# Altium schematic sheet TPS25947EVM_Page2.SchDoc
size 431 x 279 mm; Date: Not shown in title block; ApprovedBy: Not shown in title block; CheckedBy: Not shown in title block; Author: Not shown in title block; CompanyName: Not shown in title block; Engineer: Not shown in title block; Organization: Not shown in title block; Address1: Not shown in title block; Address2: Not shown in title block; Address3: Not shown in title block; Address4: Not shown in title block; DocumentNumber: 2; Revision: Use project parameter SCH_Rev; SheetNumber: 2; SheetTotal: 3; PageSetup: Record=PageOptions¦CenterHorizontal=True¦CenterVertical=True¦PrintScale=1.00¦XCorrection=1.00¦YCorrection=1.00¦PrintKind=0¦BorderSize=5000000¦LeftOffset=0¦BottomOffset=0¦Orientation=2¦PaperLength=1000¦PaperWidth=1000¦Scale=100¦PaperSource=15¦PrintQuality=600¦MediaType=1¦DitherType=10¦PaperKind=Letter¦PrintScaleMode=1
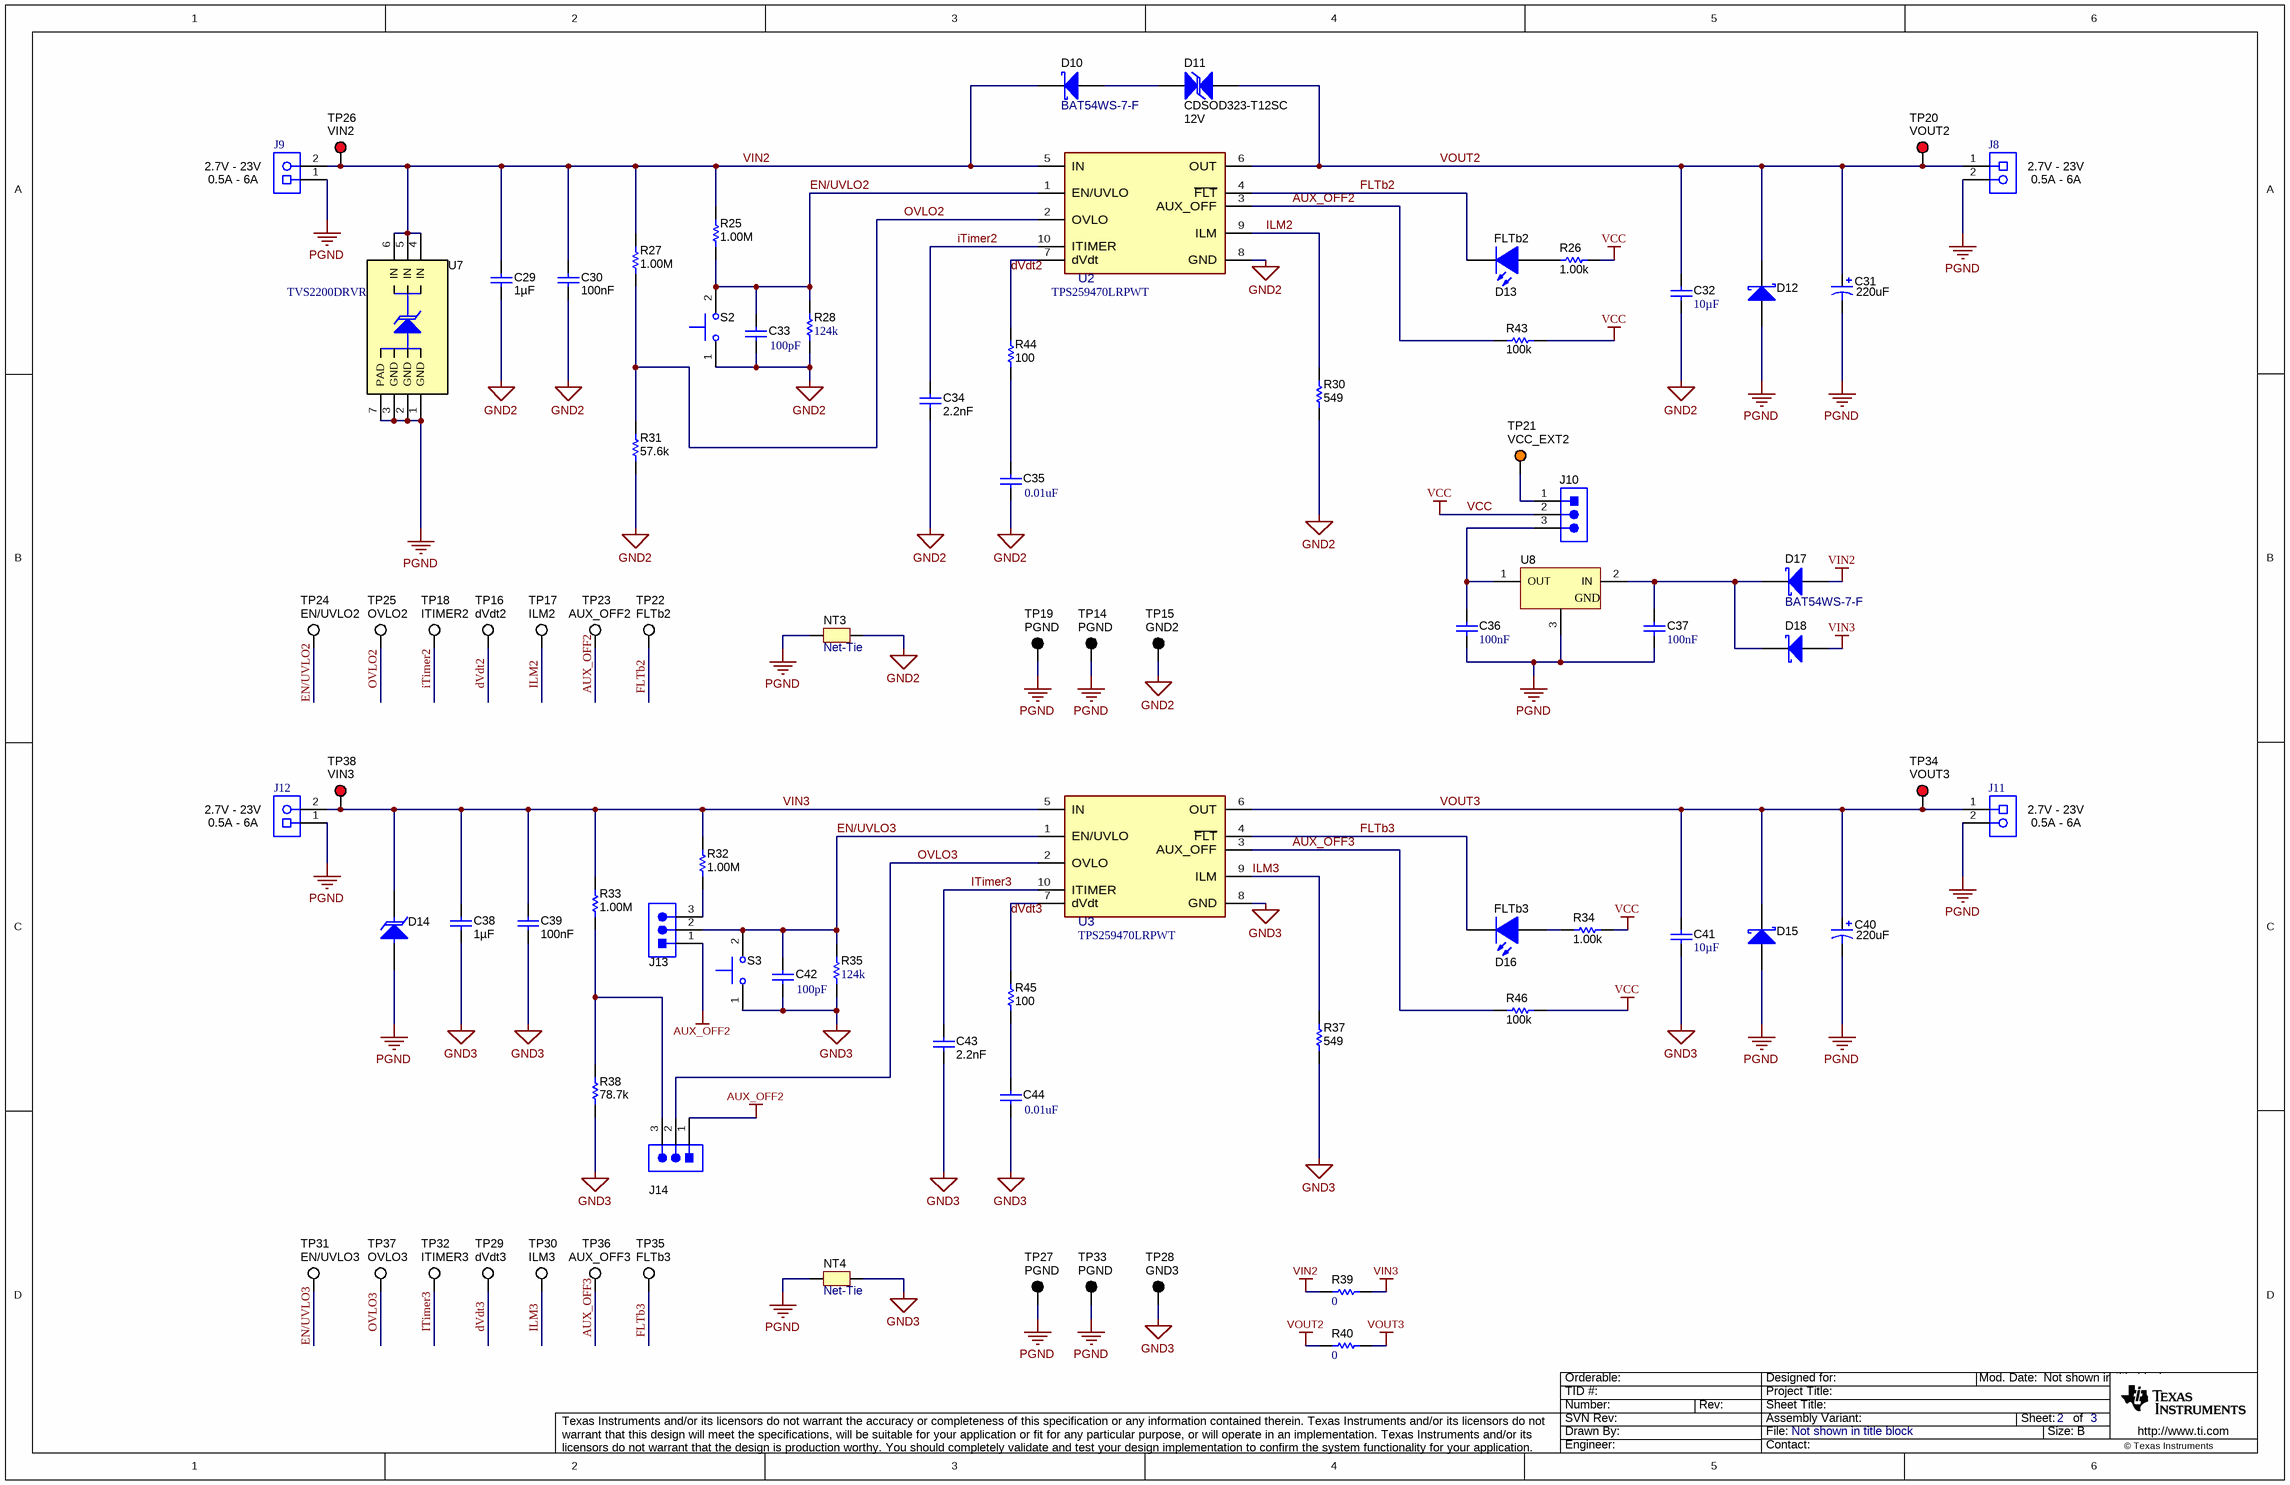
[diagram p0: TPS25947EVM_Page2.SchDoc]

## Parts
C29  Cap_F: 1µF  [0603]  (hidden comment: C1608X7R1V105K080AC)
C30  Cap_F: 100nF  [0603]  (hidden comment: C1608X7R1H104K080AA)
C31  ValueDisplayed: 220uF  [SM_RADIAL_G]  (hidden comment: EEE-FC1V221P)
C32  ValueDisplayed: 10µF  [1206_190]  (hidden comment: CGA5L1X7R1H106K160AC)
C33  ValueDisplayed: 100pF  [0603]  (hidden comment: 885012006057)
C34  Cap_F: 2.2nF  [0603]  (hidden comment: C0603C222K5RAC)
C35  ValueDisplayed: 0.01uF  [0603]  (hidden comment: GRM1885C1H103JA01D)
C36  Cap_F: 100nF  [0603]  (hidden comment: 06035C104KAT2A)
C37  Cap_F: 100nF  [0603]  (hidden comment: 06035C104KAT2A)
C38  Cap_F: 1µF  [0603]  (hidden comment: C1608X7R1V105K080AC)
C39  Cap_F: 100nF  [0603]  (hidden comment: C1608X7R1H104K080AA)
C40  ValueDisplayed: 220uF  [SM_RADIAL_G]  (hidden comment: EEE-FC1V221P)
C41  ValueDisplayed: 10µF  [1206_190]  (hidden comment: CGA5L1X7R1H106K160AC)
C42  ValueDisplayed: 100pF  [0603]  (hidden comment: 885012006057)
C43  Cap_F: 2.2nF  [0603]  (hidden comment: C0603C222K5RAC)
C44  ValueDisplayed: 0.01uF  [0603]  (hidden comment: GRM1885C1H103JA01D)
D10  BAT54WS-7-F  [SOD-323]
D11  CDSOD323-T12SC  value 12V  [SOD-323-Bi]
D12  B330A-13-F  [SMA]  (value not drawn)
D13  value FLTb2  [LED_LTST-C170_Red]  (hidden comment: LTST-C170KRKT)
D14  SMBJ16A-13-F  [SMB]  (value not drawn)
D15  B330A-13-F  [SMA]  (value not drawn)
D16  value FLTb3  [LED_LTST-C170_Red]  (hidden comment: LTST-C170KRKT)
D17  BAT54WS-7-F  [SOD-323]
D18  BAT54WS-7-F  [SOD-323]  (value not drawn)
J8  282841-2  [TEC_282841-2]  (value not drawn)
J9  282841-2  [TEC_282841-2]  (value not drawn)
J10  Header_3x1_Launchpad  [CONN_PEC03SAAN]  (value not drawn)
J11  282841-2  [TEC_282841-2]  (value not drawn)
J12  282841-2  [TEC_282841-2]  (value not drawn)
J13  Header_3x1_Launchpad  [CONN_PEC03SAAN]  (value not drawn)
J14  Header_3x1_Launchpad  [CONN_PEC03SAAN]  (value not drawn)
NT3  Net-Tie  [Net-Tie_0805_HV_NoOverlay]  (net tie, no BOM)
NT4  Net-Tie  [Net-Tie_0805_HV_NoOverlay]  (net tie, no BOM)
R25  ValueDisplayed: 1.00M  [0603]  (hidden comment: RC0603FR-071ML)
R26  ValueDisplayed: 1.00k  [0603]  (hidden comment: RC0603FR-071KL)
R27  ValueDisplayed: 1.00M  [0603]  (hidden comment: RC0603FR-071ML)
R28  ValueDisplayed: 124k  [0603]  (hidden comment: CRCW0603124KFKEA)
R30  ValueDisplayed: 549  [0603]  (hidden comment: RC0603FR-07549RL)
R31  ValueDisplayed: 57.6k  [0603]  (hidden comment: RC0603FR-0757K6L)
R32  ValueDisplayed: 1.00M  [0603]  (hidden comment: RC0603FR-071ML)
R33  ValueDisplayed: 1.00M  [0603]  (hidden comment: RC0603FR-071ML)
R34  ValueDisplayed: 1.00k  [0603]  (hidden comment: RC0603FR-071KL)
R35  ValueDisplayed: 124k  [0603]  (hidden comment: CRCW0603124KFKEA)
R37  ValueDisplayed: 549  [0603]  (hidden comment: RC0603FR-07549RL)
R38  ValueDisplayed: 78.7k  [0603]  (hidden comment: RC0603FR-0778K7L)
R39  ValueDisplayed: 0  [2512]  (hidden comment: RC6432J000CS)
R40  ValueDisplayed: 0  [2512]  (hidden comment: RC6432J000CS)
R43  ValueDisplayed: 100k  [0603]  (hidden comment: RC0603FR-07100KL)
R44  ValueDisplayed: 100  [0603]  (hidden comment: RC0603FR-07100RL)
R45  ValueDisplayed: 100  [0603]  (hidden comment: RC0603FR-07100RL)
R46  ValueDisplayed: 100k  [0603]  (hidden comment: RC0603FR-07100KL)
S2  B3U-1000P  [SW_B3U-1000P]  (value not drawn)
S3  B3U-1000P  [SW_B3U-1000P]  (value not drawn)
TP14  PGND  [Keystone5011]
TP15  GND2  [Keystone5011]
TP16  dVdt2  [Keystone5012]
TP17  ILM2  [Keystone5012]
TP18  ITIMER2  [Keystone5012]
TP19  PGND  [Keystone5011]
TP20  VOUT2  [Keystone5010]
TP21  VCC_EXT2  [Keystone5013]
TP22  FLTb2  [Keystone5012]
TP23  AUX_OFF2  [Keystone5012]
TP24  EN/UVLO2  [Keystone5012]
TP25  OVLO2  [Keystone5012]
TP26  VIN2  [Keystone5010]
TP27  PGND  [Keystone5011]
TP28  GND3  [Keystone5011]
TP29  dVdt3  [Keystone5012]
TP30  ILM3  [Keystone5012]
TP31  EN/UVLO3  [Keystone5012]
TP32  ITIMER3  [Keystone5012]
TP33  PGND  [Keystone5011]
TP34  VOUT3  [Keystone5010]
TP35  FLTb3  [Keystone5012]
TP36  AUX_OFF3  [Keystone5012]
TP37  OVLO3  [Keystone5012]
TP38  VIN3  [Keystone5010]
U2  TPS259470LRPWT  [RPW0010A-MFG]
U3  TPS259470LRPWT  [RPW0010A-MFG]
U7  TVS2200DRVR  [DRV0006A]
U8  LM3480IM3-3.3/NOPB  [DBZ0003A_N]  (value not drawn)

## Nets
AUX_OFF2: J13.1 J14.1 R43.1 TP23.1 U2.3(AUX_OFF)
GND2: C29.2 C30.2 C32.2 C33.2 C34.2 C35.2 NT3.2 R28.1 R30.1 R31.1 S2.1 TP15.1 U2.8(GND)
GND3: C38.2 C39.2 C41.2 C42.2 C43.2 C44.2 NT4.2 R35.1 R37.1 R38.1 S3.1 TP28.1 U3.8(GND)
PGND: C31.2(-) C36.2 C37.2 C40.2(-) D12.2(A) D14.2(A) D15.2(A) J8.2 J9.1 J11.2 J12.1 NT3.1 NT4.1 TP14.1 TP19.1 TP27.1 TP33.1 U7.1(GND) U7.2(GND) U7.3(GND) U7.7(PAD) U8.3(GND)
VCC: J10.2 R26.2 R34.2 R43.2 R46.2
VIN2: C29.1 C30.1 D10.1(K) D17.2(A) J9.2 R25.2 R27.2 R39.1 TP26.1 U2.5(IN) U7.4(IN) U7.5(IN) U7.6(IN)
VIN3: C38.1 C39.1 D14.1(K) D18.2(A) J12.2 R32.2 R33.2 R39.2 TP38.1 U3.5(IN)
VOUT2: C31.1(+) C32.1 D11.1 D12.1(K) J8.1 R40.1 TP20.1 U2.6(OUT)
VOUT3: C40.1(+) C41.1 D15.1(K) J11.1 R40.2 TP34.1 U3.6(OUT)
AUX_OFF3: R46.1 TP36.1 U3.3(AUX_OFF)
dVdt2: R44.2 TP16.1 U2.7(dVdt)
dVdt3: R45.2 TP29.1 U3.7(dVdt)
EN/UVLO2: C33.1 R25.1 R28.2 S2.2 TP24.1 U2.1(EN/UVLO)
EN/UVLO3: C42.1 J13.2 R35.2 S3.2 TP31.1 U3.1(EN/UVLO)
FLTb2: D13.2(K) TP22.1 U2.4(~{FLT})
FLTb3: D16.2(K) TP35.1 U3.4(~{FLT})
ILM2: R30.2 TP17.1 U2.9(ILM)
ILM3: R37.2 TP30.1 U3.9(ILM)
iTimer2: C34.1 TP18.1 U2.10(ITIMER)
ITimer3: C43.1 TP32.1 U3.10(ITIMER)
OVLO2: R27.1 R31.2 TP25.1 U2.2(OVLO)
OVLO3: J14.2 TP37.1 U3.2(OVLO)
NetC35_1: C35.1 R44.1
NetC36_1: C36.1 J10.3 U8.1(OUT)
NetC37_1: C37.1 D17.1(K) D18.1(K) U8.2(IN)
NetC44_1: C44.1 R45.1
NetD10_2: D10.2(A) D11.2
NetD13_1: D13.1(A) R26.1
NetD16_1: D16.1(A) R34.1
NetJ10_1: J10.1 TP21.1
NetJ13_3: J13.3 R32.1
NetJ14_3: J14.3 R33.1 R38.2

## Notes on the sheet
- (near J9) 2.7V - 23V
- (near J8) 2.7V - 23V
- (near J9) 0.5A - 6A
- (near J8) 0.5A - 6A
- (near J12) 2.7V - 23V
- (near J12) 0.5A - 6A
- (near J11) 2.7V - 23V
- (near J11) 0.5A - 6A

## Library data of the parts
C29 C38 = CMP-0007052-4: CAP, CERM, 1 uF, 35 V, +/- 10%, X7R, 0603; Manufacturer: TDK; TaMin_C: -55°C; Polarized: N; SizeAreaWB_mm2: 4.68; Value1: Unknown; U/M: EA; Value: 1uF; TaMax_C: 125°C; SizeZ_mm: 1; SizeX_mm: 1.6; SizeY_mm: 0.8; Value2: 35V; SizeArea_mm2: 1.28; AEC Category: Q200
C30 C39 = CMP-0007044-1: CAP, CERM, 0.1 uF, 50 V, +/- 10%, X7R, 0603; Manufacturer: TDK; TaMin_C: -55°C; ESR_ohm: 0.0296; Polarized: N; SizeAreaWB_mm2: 4.68; Value1: 0.0296 ohm; U/M: EA; Value: 0.1uF; TaMax_C: 125°C; SizeZ_mm: 1; SizeX_mm: 1.6; SizeY_mm: 0.8; Value2: 50V; SizeArea_mm2: 1.28; IRMS_A: 971.99mA; AEC Category: Q200
C31 C40 = CMP-0010667-1: CAP, AL, 220 uF, 35 V, +/- 20%, 0.15 ohm, SMD; Manufacturer: Panasonic; TaMin_C: -40°C; ESR_ohm: 1.5d; Polarized: Y; SizeAreaWB_mm2: 172.2; U/M: EA; Value: 220uF; TaMax_C: 105°C; SizeZ_mm: 10.2; SizeX_mm: 12; SizeY_mm: 10.3; Cap_Case: G; Value2: 35V; SizeArea_mm2: 123.6; CompType: Capacitor; Cap_F: 220µF; IRMS_A: 6.7dA; AEC Category: Q200
C32 C41 = CMP-0085950-1: CAP, CERM, 10 µF, 50 V,+/- 10%, X7R, AEC-Q200 Grade 1, 1206; Manufacturer: TDK; SizeZ_mm: 1.9; Value: 10uF; Value2: 50V; Cap_Case: 1206; AEC Grade: 1; TaMin_C: -55°C; U/M: EA; SizeArea_mm2: 5.12; TaMax_C: 125°C; AEC Qualified: Y; AEC Category: Q200; SizeX_mm: 3.2; SizeY_mm: 1.6; Polarized: N; SizeAreaWB_mm2: 10.92
C33 C42 = CMP-0006822-4: CAP, CERM, 100 pF, 50 V, +/- 5%, C0G/NP0, 0603; Manufacturer: Wurth Elektronik; TaMin_C: -55°C; Polarized: N; SizeAreaWB_mm2: 4.68; Value1: Unknown; U/M: EA; Value: 100pF; TaMax_C: 125°C; SizeZ_mm: 1; SizeX_mm: 1.6; SizeY_mm: 0.8; Value2: 50V; SizeArea_mm2: 1.28; CompType: Capacitor; AEC Category: Q200
C34 C43 = CMP-0006897-4: CAP, CERM, 2200 pF, 50 V, +/- 10%, X7R, 0603; Manufacturer: Kemet; TaMin_C: -55°C; Polarized: N; SizeAreaWB_mm2: 4.68; Value1: Unknown; U/M: EA; Value: 2200pF; TaMax_C: 125°C; SizeZ_mm: 1; SizeX_mm: 1.6; SizeY_mm: 0.8; Value2: 50V; SizeArea_mm2: 1.28; AEC Category: Q200
C35 C44 = CMP-0007174-4: CAP, CERM, 0.01 uF, 50 V, +/- 5%, C0G/NP0, 0603; Manufacturer: MuRata; TaMin_C: -55°C; Polarized: N; SizeAreaWB_mm2: 4.68; Value1: Unknown; U/M: EA; Value: 0.01uF; TaMax_C: 125°C; SizeZ_mm: 1; SizeX_mm: 1.6; SizeY_mm: 0.8; Value2: 50V; SizeArea_mm2: 1.28; Cap_F: 10nF; AEC Category: Q200
C36 C37 = CMP-0006802-4: CAP, CERM, 0.1 uF, 50 V, +/- 10%, X7R, 0603; Manufacturer: AVX; TaMin_C: -55°C; Polarized: N; SizeAreaWB_mm2: 4.68; Value1: Unknown; U/M: EA; Value: 0.1uF; TaMax_C: 125°C; SizeZ_mm: 1; SizeX_mm: 1.6; SizeY_mm: 0.8; Value2: 50V; SizeArea_mm2: 1.28; AEC Category: Q200
D10 D17 D18 = CMP-0028458-1: Diode, Schottky, 30 V, 0.2 A, SOD-323; Manufacturer: Diodes Inc.; Io_A: 200mA; Green_Lifecycle: Active; SizeAreaWB_mm2: 8.695; Vr_V: 30V; Green_REACh: Passed; Value1: 0.2A; TJmax_C: 125°C; U/M: EA; Value: 30V; SizeZ_mm: 1; SizeX_mm: 2.7; SizeY_mm: 1.35; Vf_V: 700mV; Value2: 0.7V; SizeArea_mm2: 3.645; AEC Category: Q101
D11 = CMP-0006058-3: Diode, TVS, Bi, 12 V, 29.5 Vc, SOD323, 2-Leads, Body 1.9x1.45mm, No Polarity Mark; Manufacturer: Bourns; Ipp: 14A; Vbr_Min: 13.3V; Vc: 29.5V; AEC Category: Q101; AEC Qualified: N; Ppk: 500W
D12 D15 = CMP-0028350-2: Diode, Schottky, 30 V, 3 A, SMA; Manufacturer: Diodes Inc.; Io_A: 3A; SizeZ_mm: 2.87; SizeAreaWB_mm2: 37.3428; Value: 30V; TJmax_C: 125°C; Green_Lifecycle: Active; SizeY_mm: 2.92; Vf_V: 5dV; Green_REACh: Passed; SizeArea_mm2: 16.3228; AEC Category: Q101; Value2: 0.5V; SizeX_mm: 5.59; RJC_CperW: 25
D13 D16 = CMP-0002829-2: LED, Red, SMD; Manufacturer: Lite-On; Type: AlInGaP; Vf_V: 2V; Io_A: 20mA; Value1: W; U/M: EA; SizeAreaWB_mm2: 6.75; SizeArea_mm2: 2.5; SizeX_mm: 2; SizeY_mm: 1.25; SizeZ_mm: 1.2
D14 = CMP-0005547-4: Diode, TVS, Uni, 16 V, 26 Vc, SMB; Manufacturer: Diodes Inc.; Value: 16V; SizeArea_mm2: 21.336; SizeY_mm: 3.81; Vbr_Min: 17.8V; Ppk: 600W; AEC Category: Q101; SizeZ_mm: 2.6; Ipp: 23.1A; SizeAreaWB_mm2: 44.156; Vc: 26V; Vbr_Max: 20.5V; SizeX_mm: 5.6
J8 J9 J11 J12 = CMP-0054973-1: Terminal Block, 2x1, 5.08mm, TH; Manufacturer: TE Connectivity; CNHeader: FALSE; Green_Lifecycle: Active; Green_REACh: Passed; CT: TRUE
J10 J13 J14 = CMP-0002338-1: Header, 100mil, 3x1, Tin, TH; PartNumber: PEC03SAAN; Manufacturer: Sullins Connector Solutions; Cert_UL: Y; CNHeader: TRUE; CT: FALSE; Current_A: 3A; Gender: Male; Green_Lifecycle: Not Set; Green_REACh: Incomplete; Pitch_mm: 2.54; Row_Count: 1; Shrouded: N; Voltage_V: 1.8kV
NT3 NT4 = CMP-0078142-2: Single point connection between nets.
R25 R27 R32 R33 = CMP-0022899-2: RES, 1.00 M, 1%, 0.1 W, 0603; Manufacturer: Yageo America; Power_W: 100mW; TempCo: 200 ppm/C; Value_Code: 1M00; U/M: EA; Value: 1.00Meg; EIA_Code: E96; Res_ohm: 1M; SizeX_mm: 1.6; SizeY_mm: 0.8; SizeZ_mm: 1; Value2: 0.1W; SizeArea_mm2: 1.28; CompType: Resistor; VDC_V: 150V; AEC Category: Q200
R26 R34 = CMP-0022895-5: RES, 1.00 k, 1%, 0.1 W, 0603; Manufacturer: Yageo; Power_W: 100mW; TempCo: 100 ppm/C; Value_Code: 1k00; Value: 1.00k; EIA_Code: E96; Res_ohm: 1k; SizeX_mm: 1.6; SizeY_mm: 0.8; SizeZ_mm: 1; Value2: 0.1W; SizeArea_mm2: 1.28; AEC Qualified: N; VDC_V: 75V; AEC Category: Q200; SizeAreaWB_mm2: 4.68
R28 R35 = CMP-0022026-4: RES, 124 k, 1%, 0.1 W, AEC-Q200 Grade 0, 0603; Manufacturer: Vishay-Dale; Power_W: 100mW; TempCo: 100 ppm/C; Value: 124k; EIA_Code: E96; SizeX_mm: 1.6; SizeY_mm: 0.8; SizeZ_mm: 1; Value2: 0.1W; SizeArea_mm2: 1.28; AEC Qualified: Y; VDC_V: 75V; AEC Category: Q200; AEC Grade: 0
R30 R37 = CMP-0023179-5: RES, 549, 1%, 0.1 W, 0603; Manufacturer: Yageo; Power_W: 100mW; TempCo: 100 ppm/C; Value_Code: 549R; Value: 549; EIA_Code: E96; SizeX_mm: 1.6; SizeY_mm: 0.8; SizeZ_mm: 1; Value2: 0.1W; SizeArea_mm2: 1.28; AEC Qualified: N; VDC_V: 75V; AEC Category: Q200; SizeAreaWB_mm2: 4.68
R31 = CMP-0023191-5: RES, 57.6 k, 1%, 0.1 W, 0603; Manufacturer: Yageo; Power_W: 100mW; TempCo: 100 ppm/C; Value_Code: 57k6; Value: 57.6k; EIA_Code: E96; SizeX_mm: 1.6; SizeY_mm: 0.8; SizeZ_mm: 1; Value2: 0.1W; SizeArea_mm2: 1.28; AEC Qualified: N; VDC_V: 75V; AEC Category: Q200; SizeAreaWB_mm2: 4.68
R38 = CMP-0023275-5: RES, 78.7 k, 1%, 0.1 W, 0603; Manufacturer: Yageo; Power_W: 100mW; TempCo: 100 ppm/C; Value_Code: 78k7; Value: 78.7k; EIA_Code: E96; SizeX_mm: 1.6; SizeY_mm: 0.8; SizeZ_mm: 1; Value2: 0.1W; SizeArea_mm2: 1.28; AEC Qualified: N; VDC_V: 75V; AEC Category: Q200; SizeAreaWB_mm2: 4.68
R39 R40 = CMP-0016034-2: RES, 0, 5%, 1 W, 2512; Manufacturer: Samsung; Power_W: 1W; TempCo: ppm/C; Value_Code: 0000; U/M: EA; Value: 0; EIA_Code: E24; SizeX_mm: 6.3; SizeY_mm: 3.2; SizeZ_mm: 0.71; SizeArea_mm2: 20.16; AEC Category: Q200
R43 R46 = CMP-0022735-5: RES, 100 k, 1%, 0.1 W, 0603; Manufacturer: Yageo; Power_W: 100mW; TempCo: 100 ppm/C; Value: 100k; EIA_Code: E96; SizeX_mm: 1.6; SizeY_mm: 0.8; SizeZ_mm: 1; Value2: 0.1W; SizeArea_mm2: 1.28; AEC Qualified: N; VDC_V: 75V; AEC Category: Q200; SizeAreaWB_mm2: 4.68
R44 R45 = CMP-0022736-4: RES, 100, 1%, 0.1 W, 0603; Manufacturer: Yageo; Power_W: 100mW; TempCo: 100 ppm/C; Value_Code: 100R; Value: 100; EIA_Code: E96; SizeX_mm: 1.6; SizeY_mm: 0.8; SizeZ_mm: 1; Value2: 0.1W; SizeArea_mm2: 1.28; AEC Qualified: N; VDC_V: 75V; AEC Category: Q200; SizeAreaWB_mm2: 4.68
S2 S3 = CMP-0002150-2: SWITCH TACTILE SPST-NO 0.05A 12V; Manufacturer: Omron Electronic Components; CurrentRating_mA: 50A; PositionCount: 1; SwitchFunction: Off-Mom
TP14 TP15 TP19 TP27 TP28 TP33 = CMP-0055148-1: Test Point, Multipurpose, Black, TH; Manufacturer: Keystone; PartNumber: 5011; CNHeader: FALSE; Green_Lifecycle: Active; Green_REACh: Passed; ContactFinish: Silver; CT: TRUE
TP16-TP18 TP22-TP25 TP29-TP32 TP35-TP37 = CMP-0055149-1: Test Point, Multipurpose, White, TH; Manufacturer: Keystone; PartNumber: 5012; CNHeader: FALSE; Green_Lifecycle: Active; Green_REACh: Passed; ContactFinish: Silver; CT: TRUE
TP20 TP26 TP34 TP38 = CMP-0055147-1: Test Point, Multipurpose, Red, TH; Manufacturer: Keystone; PartNumber: 5010; CNHeader: FALSE; Green_Lifecycle: Active; Green_REACh: Passed; ContactFinish: Silver; CT: TRUE
TP21 = CMP-0055150-1: Test Point, Multipurpose, Orange, TH; Manufacturer: Keystone; PartNumber: 5013; CNHeader: FALSE; Green_Lifecycle: Active; Green_REACh: Passed; ContactFinish: Silver; CT: TRUE
U2 U3 = CMP-0087985-1: 2.7- 23V, 5.5 A, 24.5 mΩ Reverse Current Blocking eFuse with Input Reverse Polarity Protection; Manufacturer: Texas Instruments; AEC Qualified: No; SizeZ_mm: 1mm
U7 = CMP-0077834-1: 22-V Precision Surge Protection Clamp, DRV0006A (WSON-6); Alternate Manufacturer: Texas Instruments; SizeAreaWB_mm2: 9.0; SizeZ_mm: 0.8; SizeX_mm: 2.0; SizeArea_mm2: 4.0; CompType: IC; AEC Qualified: N; AEC Category: Q200
U8 = CMP-0071020-1: 100 mA, Quasi Low-Dropout Linear Voltage Regulator, 3-pin SOT-23, Pb-Free; Manufacturer: Texas Instruments; PowerWise: N; CompType: LDO IC; PackageTopMarking: L0A*XTT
